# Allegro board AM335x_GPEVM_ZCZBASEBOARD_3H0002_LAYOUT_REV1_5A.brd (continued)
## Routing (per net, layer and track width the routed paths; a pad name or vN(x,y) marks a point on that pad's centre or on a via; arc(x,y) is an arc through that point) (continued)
HDMI_IOVCC: length 34.3
  TOP w0.305: v1(147.1,29.76) 146.98,29.76 146.54,30.19 U10.3 ; U10.46 135.29,33.19 v1(135.04,33.44) ; U10.21 v1(144.13,39.23)
  TOP w0.508: FB12.1 v1(164.88,22.26) v1(164.88,23.41) ; v1(147.1,29.76) 147.99,29.76 v1(148.12,29.88)
  BOTTOM w0.508: 147.99,29.76 v1(148.12,29.88) ; 147.99,29.76 147.99,29.26 147.61,28.88 147.61,26.07 149.39,24.29 163.99,24.29 v1(164.88,23.41) v1(164.88,22.26) ; 147.99,29.76 v1(147.1,29.76) 146.34,29.76 C151.1 ; C150.1 135.29,33.69 v1(135.04,33.44) ; v1(144.13,39.23) 144.13,38.57 C152.1
HDMI_LSOE: length 4.2
  TOP w0.121: v1(136.18,16.17) 136.35,16 U11.5
  BOTTOM w0.121: R322.1 137.45,14.9 v1(136.18,16.17)
HDMI_PCLK: length 69.5
  TOP w0.121: v1(125.39,76.87) 125.89,76.87 126.02,76.75 R307.1 ; v1(146.09,43.47) 146.09,40.6 145.27,39.79 143.9,39.79 143.63,39.52 U10.22 ; v1(144.94,48.92) 145.08,49.06 147.13,49.06 147.26,49.19 147.26,52.03 147.13,52.16 135.83,52.16 133.51,49.85 v1(131.04,49.85)
  BOTTOM w0.121: v1(146.09,43.47) 146.09,46.14 144.49,47.74 144.49,48.47 v1(144.94,48.92) ; v1(131.04,49.85) 131.04,50.84 132.32,52.12 132.32,61.88 131.69,62.51 131.69,71.3 128.29,74.7 128.29,76.89 127.93,77.25 126.66,77.25 126.28,76.87 v1(125.39,76.87)
HDMI_TX0+: length 27.6
  TOP w0.095: J10.7 149.16,9.52 149.06,9.61 148.89,9.61 148.8,9.71 148.8,11.87 146.14,14.53 144.69,14.53 144.52,14.7 U11.18 142.55,14.7 142.37,14.51 142.15,14.51 139.86,16.8 139.86,20.35 138.7,21.51 138.7,22.86 140.02,24.18 140.02,27.76 140.13,27.87 U10.62
HDMI_TX0-: length 27.6
  TOP w0.095: U10.61 139.63,27.87 139.74,27.76 139.74,24.3 138.42,22.97 138.42,21.4 139.58,20.23 139.58,16.69 142.04,14.23 142.37,14.23 142.55,14.05 U11.17 144.74,14.05 144.94,14.25 146.02,14.25 148.52,11.75 148.52,9.71 148.42,9.61 148.25,9.61 148.16,9.52 J10.9
HDMI_TX1+: length 27.6
  TOP w0.095: J10.4 150.66,9.52 150.56,9.61 150.39,9.61 150.3,9.71 150.3,11.79 145.63,16.46 144.55,16.46 144.37,16.65 U11.21 142.55,16.65 142.37,16.46 142.11,16.46 140.63,17.94 140.63,21.06 139.89,21.79 139.89,22.58 141.52,24.21 141.52,27.76 141.63,27.87 U10.65
HDMI_TX1-: length 27.6
  TOP w0.095: J10.6 149.66,9.52 149.75,9.61 149.92,9.61 150.02,9.71 150.02,11.68 145.51,16.18 144.55,16.18 144.37,16 U11.20 142.55,16 142.37,16.18 141.99,16.18 140.35,17.83 140.35,20.94 139.61,21.68 139.61,22.69 141.24,24.32 141.24,27.76 141.13,27.87 U10.64
HDMI_TX2+: length 27.6
  TOP w0.095: U10.68 143.13,27.87 143.02,27.76 143.02,23.4 141.34,21.72 141.34,18.5 142.08,17.76 142.37,17.76 142.55,17.95 U11.23 144.37,17.95 144.55,17.76 145.65,17.76 151.8,11.61 151.8,9.71 151.89,9.61 152.06,9.61 152.16,9.52 J10.1
HDMI_TX2-: length 27.6
  TOP w0.095: J10.3 151.16,9.52 151.25,9.61 151.42,9.61 151.52,9.71 151.52,11.5 145.53,17.48 144.55,17.48 144.37,17.3 U11.22 142.55,17.3 142.37,17.48 141.96,17.48 141.06,18.38 141.06,21.83 142.74,23.51 142.74,27.76 142.63,27.87 U10.67
HDMI_VSYNC: length 70.3
  TOP w0.121: v1(146.37,74.31) 146.37,74.81 146.19,74.99 145.07,74.99 144.94,74.87 144.94,73.9 144.82,73.77 144.04,73.77 143.92,73.9 143.92,75.02 143.79,75.14 143.04,75.14 142.91,75.02 142.91,73.9 142.79,73.77 142.05,73.77 141.92,73.9 141.92,74.94 R305.1 ; U10.35 137.13,38.92 136.71,39.33 135.26,39.33 133.07,41.51 133.07,43.65 134.41,44.99 134.41,46.33 134.54,46.46 135.17,46.46 135.29,46.34 135.29,44.86 135.41,44.74 135.65,44.74 135.77,44.86 135.77,46.34 135.89,46.46 136.14,46.46 136.26,46.34 136.26,44.86 136.38,44.74 136.62,44.74 136.74,44.86 136.74,46.34 136.86,46.46 137.4,46.46 137.53,46.33 137.53,44.61 137.65,44.49 138.19,44.49 138.31,44.61 138.31,46.33 138.44,46.46 141.07,46.46 141.26,46.27 v1(142.02,46.27)
  BOTTOM w0.121: v1(142.02,46.27) 142.02,54.35 142.11,54.44 145.55,54.44 145.94,54.83 145.94,72.25 146.37,72.68 v1(146.37,74.31)
HDMICONN_CEC: length 12.1
  TOP w0.121: U11.7 138.54,14.7 141.64,11.59 142.02,11.59 142.91,10.7 144.49,10.7 144.61,10.58 145.45,10.58 146.16,9.87 J10.13
HDMICONN_HPLG: length 9.5
  TOP w0.121: U11.10 138.84,12.75 140.75,10.83 140.75,9.66 v1(142.2,8.22) 142.66,8.22 142.86,8.42 J10.19
  BOTTOM w0.121: R304.2 v1(142.2,8.22)
HDMICONN_I2CSCL: length 13.7
  TOP w0.121: v1(145.38,6.26) 145.16,6.48 J10.15 145.16,9.68 144.38,10.45 142.78,10.45 141.95,11.29 141.44,11.29 138.68,14.05 U11.8
  BOTTOM w0.121: v1(145.38,6.26) R276.1
HDMICONN_I2CSDA: length 13
  TOP w0.121: U11.9 138.49,13.4 138.51,13.37 138.85,13.37 141.24,10.98 141.87,10.98 142.66,10.2 143.47,10.2 143.47,10.21 144.05,10.21 144.66,9.59 J10.16 v1(144.66,6.23)
  BOTTOM w0.121: R275.1 144.11,5.68 v1(144.66,6.23)
JTAG_EMU0: length 98.4
  TOP w0.102: v2(79.4,89) U2.C14
  TOP w0.121: v1(22.14,89.19) J2.13 ; v1(34.73,91.69) 35.17,91.69 35.37,91.5 47.08,91.5 48.45,92.86 56.14,92.86 57.23,93.95 59.28,93.95 59.91,93.32 60.94,93.32 62.14,94.53 63.83,94.53 64.67,93.69 65.46,93.69 65.96,93.18 66.14,93.18 66.31,93 67.75,93 68.52,92.23 69.98,92.23 70.3,92.55 v1(70.3,92.68) ; R582.1 v1(14.26,67.14)
  LY3 w0.133: v1(14.26,67.14) 15.66,68.54 16.19,68.54 17.27,69.62 20.68,69.62 21.83,70.77 21.83,74.86 22.3,75.33 22.3,75.7 22.03,75.97 22.03,78.4 22.65,79.01 22.65,82.45 21.83,83.27 21.83,84.44 22.58,85.2 22.58,86.84 22.32,87.1 22.32,87.47 22.58,87.74 22.58,88.11 22.14,88.55 v1(22.14,89.19) 22.14,89.64 24.98,92.48 24.98,92.98 25.49,93.48 30.16,93.48 31.95,91.69 v1(34.73,91.69)
  BOTTOM w0.102: 78.98,89 v2(79.4,89)
  BOTTOM w0.121: R71.1 v1(22.14,89.19) ; v1(70.3,92.68) 70.3,92.38 73.46,89.23 78.75,89.23 78.98,89
JTAG_EMU1: length 95.2
  TOP w0.102: 77.1,89.4 77.5,89 78.6,89 U2.B14
  TOP w0.121: v1(73.06,91.75) 73.07,91.75 73.46,91.36 73.46,90.78 73.6,90.64 74.98,90.64 75.96,89.66 76.84,89.66 77.1,89.4 ; v1(31.91,93.76) 32.57,93.76 32.88,93.46 32.88,92.85 33.35,92.38 47.14,92.38 48.11,93.36 55.92,93.36 57.31,94.75 59.45,94.75 60.23,95.53 62.36,95.53 63.08,96.26 65.33,96.26 65.75,96.68 69.1,96.68 v1(69.41,96.36) ; R583.1 v1(17.56,67.17) 18,67.17 18.13,67.3 v1(25.39,67.3) ; J2.14 v1(31.41,89.19)
  BOTTOM w0.121: v1(31.91,93.76) 31.91,89.7 v1(31.41,89.19) R70.1 30.39,85.71 26.28,81.6 26.28,68.19 v1(25.39,67.3) ; v1(73.06,91.75) 71.9,91.75 70.99,92.66 70.99,93.25 69.61,94.63 69.61,95.41 69.35,95.67 69.35,95.87 69.41,95.92 v1(69.41,96.36)
JTAG_TCK: length 100.1
  TOP w0.102: U2.A12 77.75,87 77.1,87.65
  TOP w0.121: R576.1 v1(9.18,67.22) ; v1(63.66,89) 59.85,89 59.1,89.75 56.26,89.75 54.69,91.31 49.03,91.31 47.32,89.6 35.5,89.6 35.3,89.39 v1(34.86,89.39) ; 77.1,87.65 76.33,88.42 75.37,88.42 74.62,89.17 74.4,89.39 74.36,89.39 69.49,89.39 69.49,89.4 69.26,89.4 67.94,90.72 65.63,90.72 65.51,90.84 v1(65.12,90.84)
  LY3 w0.133: v1(34.86,89.39) 34.35,89.9 31,89.9 30.44,90.46 v1(25.95,90.46) 23.1,87.62 23.1,84.98 22.96,84.83 22.96,84.31 23.17,84.1 23.17,69.12 19.42,65.37 11.04,65.37 v1(9.18,67.22)
  BOTTOM w0.121: v1(25.95,90.46) R75.2 R74.2 ; v1(65.12,90.84) 65.12,90.14 63.98,89 v1(63.66,89)
JTAG_TDI: length 112.5
  TOP w0.102: 77.1,87.12 77.63,86.59 78.61,86.59 U2.B11
  TOP w0.121: v1(21.09,94.22) 21.41,94.53 21.41,94.58 22.36,95.54 J2.3 26.07,95.54 26.45,95.92 26.45,97.32 26.71,97.57 32.02,97.57 32.04,97.6 v1(34.15,97.6) ; v1(33.9,88.23) 34.22,87.91 39.37,87.91 40.44,88.98 47.57,88.98 49.29,90.69 54.4,90.69 56.38,88.71 58.81,88.71 59.41,88.11 v1(63.66,88.11) ; v1(10.15,67.02) 10.55,67.42 10.55,67.63 R577.1 ; 77.1,87.12 76.17,88.05 75.22,88.05 75.22,88.05 74.24,89.02 74.21,89.02 72.26,89.02 71.39,88.15 71.33,88.15 v1(71.02,87.84)
  LY3 w0.133: v1(10.15,67.02) 12,68.87 13.6,68.87 15.25,70.52 20.31,70.52 20.92,71.14 20.92,88.32 20.83,88.41 20.83,88.97 20.67,89.13 20.67,89.5 21.09,89.93 v1(21.09,94.22)
  BOTTOM w0.121: v1(33.9,88.23) 33.9,88.67 33.84,88.73 33.84,97.29 v1(34.15,97.6) ; v1(63.66,88.11) 64.13,88.58 66.97,88.58 68.69,86.85 70.23,86.85 71.02,87.64 v1(71.02,87.84)
JTAG_TDO: length 98.7
  TOP w0.102: 77.1,86.55 77.45,86.2 U2.A11
  TOP w0.121: v1(11.57,67.02) 11.21,67.37 R578.1 ; J2.7 v1(25.95,93) ; 77.1,86.55 75.98,87.67 75.07,87.67 74.09,88.64 74.05,88.64 72.52,88.64 72.37,88.5 71.27,87.4 70.76,87.4 70.58,87.58 70.58,88.26 69.69,89.15 69.16,89.15 67.85,90.45 65.64,90.45 65.27,90.08 65.14,90.08 65.14,90.08 64.03,90.08 63.39,90.72 61.63,90.72 61.56,90.65 56.92,90.65 55.52,92.05 48.72,92.05 47.01,90.34 35.42,90.34 35.2,90.56 v1(34.76,90.56)
  LY3 w0.133: v1(11.57,67.02) 12.02,67.02 12.06,67.06 12.41,67.06 13.04,66.43 14.45,66.43 15.08,67.07 15.08,67.3 15.35,67.57 15.58,67.57 17.37,69.36 20.79,69.36 22.09,70.66 22.09,71.01 22.3,71.22 22.3,74.97 22.56,75.23 22.56,75.81 22.33,76.04 22.33,78.32 22.91,78.9 22.91,82.56 22.49,82.98 22.49,84.74 22.84,85.09 22.84,88.21 22.58,88.47 22.58,89.64 v1(25.95,93) 30.06,93 32.5,90.56 v1(34.76,90.56)
JTAG_TMS: length 116.1
  TOP w0.102: U2.C11 79.41,86.59 v2(79.41,87.41)
  TOP w0.121: v1(18.33,65.85) 13.65,65.85 12.23,67.27 R579.1 ; J2.1 v1(24,97.69) 24.34,98.03 33.96,98.03 33.97,98.04 34.33,98.04 34.34,98.03 42.42,98.03 43.22,98.82 55.89,98.82 56.58,98.13 61.05,98.13 61.42,98.49 63.26,98.49 63.66,98.09 64.27,98.09 64.77,98.59 67.22,98.59 67.98,99.35 68.55,99.92 68.8,99.92 68.8,99.92 v1(69.25,99.92)
  LY4 w0.121: v1(69.25,99.92) 69.25,99.47 68.87,99.1 68.87,95.6 70.9,93.58 70.9,92.5 69.89,91.49 v1(69.86,91.49)
  BOTTOM w0.102: 77.1,88.48 77.52,88.48 78.59,87.41 v2(79.41,87.41)
  BOTTOM w0.121: 77.1,88.48 73.15,88.48 71.81,89.83 71.28,89.83 69.86,91.25 v1(69.86,91.49) ; v1(24,97.69) 22.63,97.69 19.77,94.83 19.77,92.32 19.39,91.93 19.39,90.31 19.52,90.19 19.52,83.32 22.57,80.28 22.57,69.33 19.09,65.85 v1(18.33,65.85)
JTAG_TRSTN: length 108
  TOP w0.102: 77.1,86.17 77.44,85.83 78.4,85.83 78.82,85.4 U2.B10
  TOP w0.121: v1(34.28,89.05) 34.59,88.74 39.63,88.74 40.24,89.35 47.42,89.35 49.13,91.06 54.56,91.06 56.18,89.45 58.65,89.45 59.53,88.56 63.48,88.56 63.48,88.56 63.85,88.56 64.3,89.02 v1(64.71,89.02) ; 77.1,86.17 75.86,87.41 74.97,87.41 73.98,88.4 73.95,88.4 72.62,88.4 71.37,87.15 70.66,87.15 70.51,87.3 70.14,87.67 v1(70.14,87.87) ; J2.2 v1(31.41,96.81) 32.28,96.81 32.29,96.82 32.66,96.82 32.67,96.81 v1(34.28,96.81) ; R580.1 v1(13.25,67.12)
  LY3 w0.133: v1(31.41,96.81) 30.52,95.92 24.42,95.92 21.8,93.31 21.8,92.34 21.57,92.1 21.57,75.87 21.4,75.7 21.4,75.33 21.57,75.17 21.57,70.87 20.57,69.88 15.52,69.88 13.25,67.61 v1(13.25,67.12)
  BOTTOM w0.121: v1(64.71,89.02) 67.78,89.02 68.92,87.87 70.13,87.87 v1(70.14,87.87) ; v1(34.28,89.05) 34.28,89.5 34.28,89.5 34.28,96.37 34.28,96.37 v1(34.28,96.81) ; v1(31.41,96.81) R79.2
LCD_DATA0: length 4.5
  TOP w0.102: 138.01,85.25 J7.4
  TOP w0.121: 138.01,85.25 138.54,85.79 138.95,85.79 139.1,85.94 139.1,86.07 138.88,86.29 138.88,86.34 139.07,86.52 140.02,86.52 140.12,86.42 140.12,86.27 R240.1
LCD_DATA1: length 4.7
  TOP w0.102: 138.04,85.91 136.59,85.91 J7.3
  TOP w0.121: R241.1 139.23,87.03 138.11,85.91 138.04,85.91
LCD_DATA2: length 4.4
  TOP w0.102: J7.6 137.91,83.98 138.04,83.86
  TOP w0.121: 138.04,83.86 138.06,83.83 138.06,83.78 138.24,83.6 138.39,83.6 138.39,83.6 138.52,83.73 138.52,83.81 138.61,83.9 138.78,83.9 138.85,83.83 138.85,83.72 138.98,83.6 139.17,83.6 139.25,83.68 139.25,83.96 139.43,84.14 139.63,84.14 139.65,84.11 140.01,84.11 140.14,83.98 140.14,83.88 R245.1
LCD_DATA3: length 4.5
  TOP w0.121: v1(138.72,84.49) 139.1,84.87 139.61,84.87 R246.1
  BOTTOM w0.102: J7.5 136.54,84.59 137.93,84.59 138.04,84.49
  BOTTOM w0.121: v1(138.72,84.49) 138.04,84.49
LCD_DATA4: length 4.5
  TOP w0.102: 138.04,82.16 137.98,82.21 137.98,82.56 137.83,82.71 J7.8
  TOP w0.121: R251.1 140.13,81.84 140.13,82.01 140.07,82.08 139.53,82.08 139.33,82.28 139.18,82.28 139.1,82.21 139.1,82.03 139,81.93 138.86,81.93 138.63,82.16 138.44,82.16 138.3,82.01 138.18,82.01 138.04,82.16
LCD_DATA5: length 4.5
  TOP w0.121: R252.1 138.85,82.59 v1(138.59,82.84)
  BOTTOM w0.102: 138.04,83.27 137.96,83.35 136.56,83.35 J7.7
  BOTTOM w0.121: 138.04,83.27 138.47,82.84 v1(138.59,82.84)
LCD_DATA6: length 4.5
  TOP w0.102: J8.15 130.67,77.63 130.52,77.79 130.52,78.32
  TOP w0.121: R270.1 129.15,77.76 129.27,77.63 129.27,77.53 129.4,77.41 129.93,77.41 130.06,77.53 130.06,78.32 130.19,78.45 130.39,78.45 130.52,78.32
LCD_DATA7: length 8.6
  TOP w0.121: R259.1 129.2,82.84 v1(129.49,82.55)
  LY3 w0.102: 130.57,81.44 J8.9
  LY3 w0.133: v1(129.49,82.55) 128.1,82.55 127.75,82.9 127.75,83.2 127.88,83.32 129.96,83.32 130.09,83.2 130.09,81.57 130.21,81.44 130.57,81.44
LCD_DATA8: length 9.4
  TOP w0.102: 130.72,82.08 133.46,82.08 133.59,81.95 ; 133.59,80.94 133.49,80.83 132.19,80.83 131.53,80.17 J8.11
  TOP w0.121: R262.1 129.53,80.81 130.14,81.42 130.14,81.78 130.26,81.9 130.26,81.9 130.44,82.08 130.72,82.08 ; 133.59,81.95 133.72,81.95 133.84,81.83 133.84,81.14 133.64,80.94 133.59,80.94
LCD_DATA9: length 4.1
  TOP w0.102: R266.1 129.2,78.78 129.31,78.68 129.31,78.14 129.41,78.04 129.61,78.04 129.71,78.14 129.71,78.68 129.81,78.78 130.54,78.78 130.67,78.9 J8.13
LCD_DATA10: length 10.1
  TOP w0.121: v1(138.72,80.37) 139.18,79.91 139.18,79.67 139.31,79.54 R256.1
  LY3 w0.102: 138.14,81.32 138.01,81.44 J7.10
  LY3 w0.133: 138.14,81.32 138.47,80.99 139.99,80.99 140.09,80.89 140.09,78.68 139.97,78.55 138.85,78.55 138.72,78.68 v1(138.72,80.37)
LCD_DATA11: length 10.7
  TOP w0.121: R267.1 139.1,77.13 v1(138.89,77.34)
  LY3 w0.102: J7.16 138.01,77.63 138.29,77.91 141.67,77.91
  LY3 w0.133: 141.67,77.91 141.79,77.79 141.79,76.62 141.67,76.49 139.13,76.49 138.89,76.73 v1(138.89,77.34)
LCD_DATA12: length 13.1
  TOP w0.121: v1(138.59,81.57) 138.34,81.32 138.34,81.19 138.46,81.07 139.74,81.07 139.86,80.94 R257.1
  BOTTOM w0.102: 138.04,82.42 137.97,82.42 137.63,82.08 136.56,82.08 J7.9
  BOTTOM w0.121: v1(138.59,81.57) 139.31,81.57 139.51,81.77 139.51,84.62 139.41,84.72 139.27,84.72 139.18,84.62 139.18,82.21 139.05,82.08 138.29,82.08 138.21,82.16 138.21,82.3 138.09,82.42 138.04,82.42
LCD_DATA13: length 18.6
  TOP w0.121: R258.1 129.27,81.83 v1(129.53,81.57)
  LY3 w0.102: J8.10 133.59,81.44 ; 130.72,80.57 130.99,80.83 133.59,80.83
  LY3 w0.133: 133.59,81.44 133.67,81.52 133.67,84.45 133.79,84.57 133.96,84.57 134.08,84.45 134.08,84.21 134.23,84.06 134.4,84.06 134.53,83.93 134.53,83.11 134.4,82.98 134.28,82.98 134.15,82.85 134.15,82.57 134.28,82.45 134.43,82.45 134.56,82.32 134.56,82.04 134.43,81.91 134.2,81.91 134.07,81.79 134.07,81.51 134.2,81.38 134.38,81.38 134.5,81.25 134.5,80.96 134.38,80.83 133.59,80.83 ; 130.72,80.57 130.4,80.57 130.26,80.7 130.26,80.83 130.13,80.97 129.37,80.97 128.41,81.93 128.41,82.02 128.54,82.16 128.94,82.16 v1(129.53,81.57)
LCD_DATA14: length 9.2
  TOP w0.102: 138.04,80.17 J7.12 ; 138.04,79.72 138.04,78.88 138.04,78.87
  TOP w0.121: 138.04,79.72 138.16,79.84 138.16,80.05 138.04,80.17 ; R260.1 140.25,78.78 140.25,78.85 140.06,79.03 139.65,79.03 139.57,79.12 139.4,79.12 139.25,78.97 139.25,78.35 139.14,78.24 138.98,78.24 138.87,78.35 138.87,79.72 138.75,79.84 138.57,79.84 138.44,79.72 138.44,78.44 138.33,78.32 138.16,78.32 138.04,78.44 138.04,78.87
LCD_DATA15: length 24.4
  TOP w0.121: R254.1 v1(129.7,83.86)
  LY3 w0.102: 130.55,82.82 130.65,82.71 J8.7
  LY3 w0.133: v1(129.7,83.86) 127.14,83.86 127.01,83.98 127.01,85.41 127.14,85.55 129.82,85.55 129.96,85.68 129.96,85.95 129.82,86.08 127.14,86.08 127.01,86.21 127.01,86.47 127.14,86.6 127.4,86.6 127.65,86.85 127.93,86.85 128.19,86.6 130.29,86.6 130.42,86.47 130.42,85.29 130.28,85.15 128.29,85.15 128.15,85.02 128.15,84.75 128.29,84.62 130.28,84.62 130.42,84.49 130.42,82.95 130.55,82.82
LCD_DATA16: length 64.1
  TOP w0.121: R253.1 97.53,93.41 98.36,93.41 98.64,93.69 98.64,94.62 100.06,96.04 103.21,96.04 104.99,97.82 113.7,97.82 114.03,98.16 115.17,98.16 115.29,98.28 115.29,99.49 115.41,99.61 115.65,99.61 115.77,99.49 115.77,99.32 115.89,99.2 119.3,99.2 119.42,99.08 119.42,98.84 119.3,98.72 115.89,98.72 115.77,98.6 115.77,98.28 115.89,98.16 v1(116.34,98.16)
  LY4 w0.133: v1(117,86.38) 117,86.96 116.78,87.18 116.78,93.84 116.79,93.86 116.79,94.43 116.47,94.75 116.47,95.62 116.34,95.75 115.79,95.75 115.66,95.88 115.66,96.15 115.79,96.28 116.34,96.28 116.47,96.42 116.47,98.03 v1(116.34,98.16)
  BOTTOM w0.102: 130.72,82.16 130.77,82.1 132.09,82.1 132.7,82.71 J8.8
  BOTTOM w0.121: v1(117,86.38) 117.26,86.63 126.85,86.63 127.14,86.35 127.14,84.34 127.7,83.78 129.1,83.78 130.72,82.16
LCD_DATA17: length 46.1
  TOP w0.121: R248.1 103.27,94.27 104.79,95.79 117.25,95.79 117.54,96.07 v1(118.41,96.07)
  LY4 w0.133: v1(118.41,96.07) 118.41,95.38 118.54,95.24 119.54,95.24 119.67,95.11 119.67,94.84 119.54,94.71 118.54,94.71 118.41,94.58 118.41,94.31 118.54,94.18 119.54,94.18 119.67,94.04 119.67,93.78 119.54,93.64 118.54,93.64 118.41,93.51 118.41,89.95 118.02,89.56 v1(118.02,87.46)
  BOTTOM w0.102: 130.72,84.75 130.72,84.54 131.28,83.98 J8.5
  BOTTOM w0.121: v1(118.02,87.46) 118.97,87.46 119.16,87.28 119.52,87.28 119.71,87.46 127.7,87.46 130.03,85.13 130.34,85.13 130.72,84.75
LCD_DATA18: length 53.5
  TOP w0.102: J8.6 132.12,83.35 130.85,83.35 130.72,83.48
  TOP w0.121: v1(98.92,89.04) 98.92,88.9 98.79,88.78 98,88.78 97.9,88.87 97.52,88.87 97.51,88.86 R247.1 ; v1(106.78,88.24) 106.78,87.26 108.11,85.93 108.11,83.4 109.55,81.96 112.77,81.96 114.37,83.56 122.4,83.56 122.68,83.84 122.85,83.84 123.19,83.5 123.36,83.5 123.53,83.67 123.53,83.84 123.19,84.18 123.19,84.35 123.36,84.52 123.53,84.52 123.87,84.19 124.04,84.19 124.21,84.36 124.21,84.53 123.87,84.86 123.87,85.03 124.04,85.21 124.21,85.21 124.55,84.87 124.72,84.87 124.89,85.04 124.89,85.21 124.55,85.55 124.55,85.72 124.72,85.89 124.9,85.89 125.23,85.55 125.4,85.55 125.57,85.72 125.57,85.89 125.24,86.23 125.24,86.4 126,87.16 127.55,87.16 127.67,87.03 127.67,86.3 127.55,86.18 126.17,86.18 126.05,86.06 126.05,85.81 126.17,85.69 127.55,85.69 127.67,85.57 127.67,85.25 128.48,84.45 129.75,84.45 130.72,83.48
  BOTTOM w0.121: v1(98.92,89.04) 104.91,89.04 105.71,88.24 106.77,88.24 v1(106.78,88.24)
LCD_DATA19: length 30.1
  TOP w0.121: R264.1 112.41,86.12 115,86.12 115.18,85.94 116.82,85.94 116.82,85.94 117.19,85.94 117.19,85.94 117.68,85.94 118.33,85.29 v1(118.77,85.29)
  LY3 w0.102: 130.63,79.96 131.03,79.56 133.16,79.56 133.82,78.9 J7.13
  LY3 w0.133: 130.63,79.96 129.88,80.71 129.09,80.71 126.55,83.25 126.55,85.91 125.34,87.13 122.06,87.13 120.22,85.29 v1(118.77,85.29)
LCD_DATA20: length 26.6
  TOP w0.102: 130.72,85.25 J8.3
  TOP w0.121: R243.1 112.48,82.71 112.84,83.07 112.84,83.36 112.72,83.48 112.48,83.48 112.36,83.6 112.36,83.93 112.48,84.05 122.19,84.05 125.8,87.67 127.93,87.67 128.18,87.41 128.18,85.52 128.75,84.95 130.28,84.95 130.59,85.25 130.72,85.25
LCD_DATA21: length 35.6
  TOP w0.102: 130.72,85.89 132.12,85.89 J8.4
  TOP w0.121: 130.72,85.89 130.02,85.19 128.96,85.19 128.43,85.73 128.43,87.52 128.31,87.64 128.31,87.67 128.06,87.92 125.7,87.92 122.09,84.3 114.34,84.3 113.96,84.69 113.96,84.9 114.08,85.03 117.21,85.03 117.33,85.15 117.33,85.57 117.21,85.69 116.72,85.69 116.72,85.69 112.74,85.69 112.3,85.26 111.84,85.26 111.34,85.76 R242.1
LCD_DATA22: length 52.5
  TOP w0.121: R263.1 v1(104.81,91.6)
  LY3 w0.133: v1(140.17,89.65) 139.85,89.96 139.85,90.01 139.83,90.01 139.56,90.28 139.56,90.63 139.08,91.12 v1(137.36,91.12)
  BOTTOM w0.102: 138.04,78.9 J7.14
  BOTTOM w0.121: 138.04,78.9 139,78.9 140.8,80.7 140.8,88.91 140.48,89.22 140.48,89.34 v1(140.17,89.65) ; v1(137.36,91.12) 136.97,91.12 136.18,90.33 132.49,90.33 131.9,90.92 131.86,90.92 131.07,91.71 130.05,91.71 129.12,90.77 128.68,90.33 125.3,90.33 124.97,90.66 112.1,90.66 111.85,90.91 108.62,90.91 107.92,91.6 v1(104.81,91.6)
LCD_DATA23: length 44.4
  TOP w0.121: v1(128.89,87.59) 128.13,88.35 128.13,88.48 128.01,88.6 120.22,88.6 v1(119.34,87.72) ; R261.1 108.77,91.6 110.3,93.13 114.92,93.13 115.05,93 118.12,93 118.53,93.41 v1(119.98,93.41)
  LY3 w0.102: v1(128.89,87.59) 129.6,87.59 129.64,87.63 129.74,87.63 129.78,87.67 130.14,87.67 130.21,87.59 130.54,87.59 130.72,87.41 133.92,87.41 134.81,86.52 134.81,85.36 135.04,85.13 135.04,80.25 135.11,80.17 J7.11
  LY4 w0.133: v1(119.98,93.41) 119.34,92.77 v1(119.34,87.72)
LCD_DEN: length 20.6
  TOP w0.102: v1(130.01,76.36) 129.32,76.36 R273.1
  BOTTOM w0.102: 133.72,77.99 133.72,77.48 133.59,77.36 133.59,77.33 ; 130.72,77 130.73,76.99 133.53,76.99 133.59,77.05 ; 133.57,75.14 133.57,75.58 133.44,75.71 130.72,75.71 ; J8.17 130.72,76.36
  BOTTOM w0.121: 130.72,77 130.64,77 130.52,77.12 130.52,79.16 130.39,79.29 130.14,79.29 130.01,79.16 v1(130.01,76.36) ; 133.72,77.99 133.84,78.12 134.12,78.12 134.25,77.99 134.25,75.19 134.08,75.02 133.7,75.02 133.57,75.14 ; 130.72,75.71 130.54,75.71 130.42,75.84 130.42,76.24 130.54,76.36 130.72,76.36 ; 133.59,77.33 133.59,77.05
LCD_HSYNC: length 6
  TOP w0.102: 130.72,75.7 132.09,75.7 J8.18
  TOP w0.121: 130.72,75.7 130.62,75.7 130.45,75.54 130.09,75.54 129.96,75.41 129.96,75.18 130.09,75.06 130.16,75.06 130.29,74.93 130.29,74.58 130.16,74.46 129.55,74.46 129.3,74.71 R272.1
LCD_I2C_SCL: length 19.6
  TOP w0.102: 133.59,78.07 J8.14
  TOP w0.121: 133.59,78.07 133.59,74.64 134,74.23 135.34,74.23 138.29,74.23 138.44,74.37 139.01,74.37 140.06,73.32 146.09,73.32 146.85,72.55 146.85,71.79
LCD_I2C_SDA: length 17.1
  TOP w0.102: 138.34,77 136.56,77 J7.15
  TOP w0.121: 138.34,77 138.72,76.62 142.02,76.62 142.99,75.65 146.44,75.65 147.23,74.87 147.23,73.67 147.35,73.55 147.35,71.03 146.85,70.52
LCD_PCLK: length 4.4
  TOP w0.102: J8.16 132.63,77.63 131.99,77 130.72,77
  TOP w0.121: R269.1 128.94,77 130.72,77
LCD_VSYNC: length 4.5
  TOP w0.102: J7.17 136.59,75.7 138.04,75.7
  TOP w0.121: R271.1 138.77,74.97 138.04,75.7
LCDA_PIN18: length 2.8
  TOP w0.102: 138.04,76.36 J7.18
  TOP w0.121: R274.2 138.85,75.98 138.47,76.36 138.04,76.36
MCASP0_ACLKR: length 27
  TOP w0.121: R218.1 v1(70.62,107.48)
  BOTTOM w0.121: v1(70.62,107.48) 70.62,108.13 70.82,108.32 70.82,116.79 67.26,120.34 67.21,120.34 67.22,120.35 J6.17
MCASP0_ACLKX: length 7.1
  TOP w0.121: v1(87.84,131.23) 87.54,131.53 R194.2
  BOTTOM w0.121: v1(87.84,131.23) 88.49,130.58 88.49,126.59 J6.1
MCASP0_AHCLKR: length 45.2
  TOP w0.121: R211.2 82.21,155.61 81.68,155.09 71.02,155.09 v1(70.52,155.59)
  BOTTOM w0.121: v1(70.52,155.59) 70.16,155.23 70.16,151.82 69.89,151.55 69.89,148.14 70.16,147.87 70.16,140.63 70,140.46 70,136.4 71.2,135.19 71.2,127.78 72.3,126.68 J6.13
MCASP0_AHCLKX: length 20.9
  TOP w0.121: J6.27 v1(45.5,125.64) ; R234.1 v1(45.17,114.59)
  BOTTOM w0.121: v1(45.5,125.64) 45.5,119.75 45.17,119.42 v1(45.17,114.59)
MCASP0_AXR0: length 1.8
  BOTTOM w0.121: R203.2 J6.7
MCASP0_AXR1: length 8.4
  TOP w0.121: R227.1 52.48,126.66 57.43,126.66 58.46,125.64 J6.23
MCASP0_FSR: length 31.2
  TOP w0.121: v1(68.36,123.86) 64.78,123.86 63.83,124.81 62.97,124.81 J6.21 ; v1(73.44,103.03) 73.7,102.78 R224.1
  BOTTOM w0.121: v1(68.36,123.86) 68.79,123.43 68.79,122.54 69.57,121.77 70.27,121.77 72.86,119.18 72.86,104.96 73.44,104.38 v1(73.44,103.03)
MCASP0_FSX: length 1.8
  BOTTOM w0.121: R199.2 J6.5
MMC2_CLK: length 39.9
  TOP w0.121: U28.13 21.76,106.66 4.89,106.66 4.61,106.94 4.61,107.33 4.74,107.45 7.64,107.45 7.76,107.58 7.76,107.99 7.64,108.11 v1(4.61,108.11)
  BOTTOM w0.121: R485.1 5.12,111.16 4.74,110.78 4.1,110.78 3.85,110.53 3.85,106.72 3.97,106.59 7.81,106.59 7.94,106.72 7.94,107.2 7.81,107.33 5.8,107.33 5.68,107.45 5.68,108.42 5.55,108.55 4.74,108.55 4.61,108.42 v1(4.61,108.11)
MMC2_CMD: length 40.1
  TOP w0.121: U28.12 20.44,107.37 19.98,106.91 17.87,106.91 17.74,107.04 17.74,107.83 17.61,107.96 13.63,107.96 13.5,107.83 13.5,107.56 13.63,107.43 16.8,107.43 16.93,107.3 16.93,107.04 16.8,106.91 8.14,106.91 8.01,107.04 8.01,109 7.89,109.13 4.74,109.13 4.62,109 4.62,108.88 4.49,108.75 3.85,108.75 3.59,109 3.59,109.51 2.83,110.27 2.83,115.43 2.96,115.56 3.62,115.56 3.75,115.43 3.75,113.58 3.87,113.45 v1(4.36,113.45)
  BOTTOM w0.121: R486.1 v1(4.36,113.45)
MMC2_D0: length 40.6
  TOP w0.121: v1(4.36,116.88) 4.04,116.88 3.91,116.75 3.91,116.12 3.79,115.99 3.49,115.99 3.36,116.12 3.36,119.26 3.24,119.39 2.7,119.39 2.58,119.26 2.58,108.62 4.78,106.42 19.74,106.42 20.81,105.35 21.98,105.35 22.27,105.64 U28.14
  BOTTOM w0.121: v1(4.36,116.88) 4.99,116.24 4.99,115.86 5.12,115.73 R487.1
MMC2_D1: length 39.8
  TOP w0.121: U28.15 22.77,105.32 22.52,105.07 20.55,105.07 19.45,106.17 4.65,106.17 2.32,108.5 2.32,119.7 2.45,119.82 3.54,119.82 3.67,119.7 3.67,118.53 3.8,118.4 4.36,118.4 4.48,118.53 v1(4.48,119.16)
  BOTTOM w0.121: R488.1 v1(4.48,119.16)
MMC2_D2: length 39.5
  TOP w0.121: U28.8 20.47,109.37 19.87,109.97 v1(19.26,109.97) ; v1(18.63,105.7) 18.41,105.92 4.52,105.92 2.07,108.37 2.07,119.9 2.48,120.31 v1(4.48,120.31)
  BOTTOM w0.121: v1(18.63,105.7) 18.63,108.22 19.26,108.85 v1(19.26,109.97) ; R489.1 v1(4.48,120.31)
MMC2_D3: length 40.5
  TOP w0.121: v1(19.34,107.86) 19.85,108.37 U28.10 ; v1(19.34,105.65) 19.34,105.62 18.98,105.26 18.41,105.26 17.99,105.67 4.38,105.67 1.82,108.24 1.82,120.56 v1(4.36,123.1)
  BOTTOM w0.121: R490.1 5.12,123.1 v1(4.36,123.1) ; v1(19.34,107.86) v1(19.34,105.65)
MMC2_SDIO_SEL: length 3.4
  TOP w0.121: R515.1 R516.2 26.31,109.87 U28.24
MMC_CD: length 71.8
  TOP w0.121: v1(66.55,92.3) 66.55,92.3 67.75,92.3 69.02,91.03 69.97,91.03 70.36,90.64 71.79,90.64 72.3,91.15 R380.1 ; J13.15 64.3,146.44 64.76,145.99 64.76,144.21 64.63,144.08 64.28,144.08 U21.3 64.14,144.18 R378.1 v1(62.27,144.18)
  BOTTOM w0.121: v1(66.55,92.3) 66.56,92.31 66.56,92.77 66.39,92.94 66.39,99.28 66.5,99.38 66.5,101.95 66.91,102.36 66.91,105.22 66.21,105.92 66.21,117.76 60.94,123.03 60.94,133.97 62.52,135.55 62.52,136.62 62.46,136.68 62.46,137.77 63.16,138.47 63.92,138.47 64.43,138.98 64.43,143.04 63.28,144.18 v1(62.27,144.18)
MMC_CLK: length 42.1
  TOP w0.121: J13.20 53.03,149.78 53.15,149.9 56.18,149.9 56.3,149.78 56.3,148.58 J13.5 56.37,143.72 56.68,143.42 U19.1 57.71,142.94 57.57,142.8 57.57,141.92 57.7,141.79 60.29,141.79 61.07,142.58 65.23,142.58 66.54,143.89 72.68,143.89 72.88,143.68 77.61,143.68 77.82,143.89 81.3,143.89 81.8,144.39 81.81,144.39 82.36,144.94 83.21,144.94 v1(83.53,145.25)
  BOTTOM w0.121: R398.1 83.6,145.17 v1(83.53,145.25)
MMC_CMD: length 51.3
  TOP w0.121: v1(58.97,145.58) 58.71,145.32 U19.7 ; v1(55.41,150.85) 55.34,150.79 49.6,150.79 48.88,150.06 J13.2 48.73,148.35 48.73,147.28 v1(48.55,147.1) ; J13.17 v1(59.73,147.11)
  LY3 w0.133: v1(80.78,145.55) 74.59,145.55 73.95,146.19 64.76,146.19 64.08,145.51 62.97,145.51 62.8,145.68 59.65,145.68 59.55,145.58 v1(58.97,145.58)
  BOTTOM w0.121: R366.1 v1(48.55,147.1) ; v1(80.78,145.55) 81.19,145.15 R397.1 ; v1(55.41,150.85) 55.41,150.79 55.54,150.66 56.68,150.66 56.81,150.53 56.81,150.28 56.93,150.16 59.48,150.16 60.36,151.04 61.51,151.04 61.63,150.91 61.63,148.75 61.51,148.63 59.85,148.63 J13.17 v1(59.73,147.11) 58.97,146.35 v1(58.97,145.58)
MMC_D0: length 47.7
  TOP w0.121: v1(77.99,145.1) 77.99,144.41 77.51,143.93 72.99,143.93 72.78,144.13 66.44,144.13 65.14,142.84 60.77,142.84 60.03,142.1 58.44,142.1 v1(58.01,142.53) 58.01,142.84 58.13,142.96 58.13,143.34 U19.2 ; v1(61.38,147.1) 61.38,148.42 J13.7 61.12,148.68 61.12,149.77 61,149.9 56.67,149.9 56.43,150.14 50.96,150.14 50.53,149.71 J13.22 50.68,148.34 50.68,147.26 v1(50.84,147.1)
  BOTTOM w0.121: v1(50.84,147.1) R367.1 ; v1(77.99,145.1) 78.02,145.1 R399.1 ; v1(61.38,147.1) 61.38,146.57 60.95,146.14 60.69,146.14 59.37,144.82 58.58,144.82 58.32,144.55 58.32,142.84 v1(58.01,142.53)
MMC_D1: length 42.2
  TOP w0.121: v1(49.69,147.1) 49.69,148.47 J13.23 49.72,150.01 50.1,150.39 56.56,150.39 56.81,150.15 62.87,150.15 63,150.02 J13.8 63,146.95 61.89,145.83 61.89,145.21 60.31,143.63 60.31,142.86 59.88,142.43 58.94,142.43 v1(58.8,142.57) 58.71,142.66 U19.3
  LY3 w0.133: v1(71.03,145.2) 69.73,143.89 66.68,143.89 65.35,142.57 v1(58.8,142.57)
  BOTTOM w0.121: R368.1 v1(49.69,147.1) ; R400.1 v1(71.03,145.2)
MMC_D2: length 42.7
  TOP w0.121: v1(58.33,150.91) 57.7,151.54 47.66,151.54 46.45,150.34 44.42,150.34 43.88,149.79 J13.9 43.85,148.48 v1(43.85,147.1) ; U19.6 59.98,144.69 v1(60.18,144.89) 62.15,146.86 v1(62.15,147.1) J13.24
  LY3 w0.133: v1(60.18,144.89) 62.55,144.89 63.3,144.14 66.44,144.14 66.51,144.21 67.18,144.21 v1(68.19,145.22)
  BOTTOM w0.121: R369.1 v1(43.85,147.1) ; v1(68.19,145.22) 68.19,145.2 68.49,144.91 R401.1 ; v1(62.15,147.1) 62.15,151.28 61.51,151.93 59.35,151.93 v1(58.33,150.91)
MMC_D3: length 41.8
  TOP w0.121: U19.8 v1(58.21,145.45) 58.21,145.96 58.58,146.34 60.17,146.34 60.52,146.69 v1(60.52,147.13) J13.16 ; v1(46.38,147.12) J13.1 46.45,148.58 46.45,149.83 47.92,151.29 57.06,151.29 v1(57.44,150.91)
  LY3 w0.133: v1(58.21,145.45) 58.52,145.13 58.78,145.13 59.79,145.13 60,145.34 62.61,145.34 63.44,144.51 65.42,144.51 66.1,145.2 v1(66.97,145.2)
  BOTTOM w0.121: v1(60.52,147.13) 61.89,148.5 61.89,151.04 61.25,151.68 59.85,151.68 59.6,151.42 59.6,150.66 59.34,150.4 57.82,150.4 57.44,150.78 v1(57.44,150.91) ; R365.1 46.38,147.85 v1(46.38,147.12) ; R396.1 v1(66.97,145.2)
MMC_D4: length 49.4
  TOP w0.121: U20.1 72.71,148.87 72.71,148.6 v1(72.94,148.37) ; v1(72.17,163.23) 65.19,163.23 64.81,163.61 64.81,167.04 63.54,168.31 48.3,168.31 47.6,167.62 J13.10 v1(47.6,164.25)
  BOTTOM w0.121: v1(72.17,163.23) 72.17,152.95 72.55,152.56 72.55,148.75 v1(72.94,148.37) ; v1(47.6,164.25) 47.6,165.2 R370.1
MMC_D5: length 45.6
  TOP w0.121: v1(50.12,164.25) 50.12,165.48 J13.11 50.1,167.45 50.58,167.93 63.16,167.93 64.3,166.79 64.3,163.36 64.93,162.72 v1(73.06,162.72) ; U20.2 v1(73.32,149.52)
  BOTTOM w0.121: v1(73.06,162.72) 73.06,150.53 73.32,150.28 v1(73.32,149.52) ; v1(50.12,164.25) 50.12,165.21 R371.1
MMC_D6: length 34.4
  TOP w0.121: v1(57.6,164.31) J13.12 57.6,166.44 57.57,166.47 57.57,166.79 57.95,167.17 62.52,167.17 63.28,166.41 63.28,162.85 63.98,162.15 v1(71.16,162.15) ; v1(70.52,150.15) 70.65,150.02 U20.7
  BOTTOM w0.121: v1(71.16,162.15) 71.16,154.98 70.52,154.34 v1(70.52,150.15) ; v1(57.6,164.31) 57.6,165.23 R372.1
MMC_D7: length 32
  TOP w0.121: v1(60.11,164.38) 60.11,165.49 J13.13 60.1,166.44 60.2,166.53 62.39,166.53 62.9,166.03 62.9,162.72 63.92,161.71 69.89,161.71 70.14,161.45 v1(71.67,161.45) ; U20.8 70.65,149.52 v1(70.52,149.39)
  BOTTOM w0.121: v1(70.52,149.39) 70.96,149.83 70.96,154.02 71.67,154.72 v1(71.67,161.45) ; R373.1 v1(60.11,164.38)
MMC_WP: length 58.1
  TOP w0.121: R379.1 76.02,106.46 75.77,106.71 70.77,106.71 70.01,105.96 v1(67.22,105.96) ; U21.5 65.5,145.17 v1(65.5,145.58) J13.14
  BOTTOM w0.121: v1(67.22,105.96) 66.71,106.47 66.71,118.33 63.48,121.55 63.43,121.55 62.39,122.59 62.39,124.55 63.09,125.25 63.09,126.03 62.53,126.59 62.39,126.59 61.19,127.79 61.19,128.57 61.24,128.63 61.24,129.19 61.89,129.84 61.89,133.85 64.67,136.63 64.67,144.75 v1(65.5,145.58)
MVRK_GPIO1_D0: length 6.4
  TOP w0.121: R437.1 114.34,161.07 J16.2
MVRK_GPIO1_D1: length 75.9
  TOP w0.121: v1(104.94,155.1) 104.94,155.31 104.05,156.2 104.05,163.61 104.3,163.87 109,163.87 J16.4
  LY4 w0.133: v1(104.94,155.1) 105.59,154.45 105.59,123.86 104.25,122.52 104.25,119.85 104.56,119.54 104.56,114.92 102.27,112.64 v1(102.27,110.08)
  BOTTOM w0.121: v1(102.27,110.08) 103.21,109.14 103.21,101.71 103.75,101.18 103.75,98.02 103.87,97.89 R439.1
MVRK_GPIO1_D2: length 72.8
  TOP w0.121: v1(104.94,154.34) 105.57,154.98 105.57,155.99 104.43,157.13 104.43,163.24 104.81,163.61 107.61,163.61 107.86,163.36 J16.6
  LY4 w0.133: v1(101.45,110.08) 101.45,115.57 101.8,115.92 101.8,121.08 105.14,124.42 105.14,154.14 v1(104.94,154.34)
  BOTTOM w0.121: R440.1 102.78,98.72 102.47,99.03 102.47,109.06 v1(101.45,110.08)
MVRK_GPIO1_D3: length 67.4
  TOP w0.121: J16.8 106.24,161.55 106.24,154.31 v1(106.21,154.28)
  LY4 w0.133: v1(103.1,110.08) 103.1,112.57 104.89,114.36 104.89,119.75 104.59,120.05 104.59,122.19 105.85,123.46 105.85,153.92 v1(106.21,154.28)
  BOTTOM w0.121: v1(103.1,110.08) 103.54,109.64 103.54,103.85 103.86,103.53 103.86,101.64 105.23,100.27 105.23,99.45 105.32,99.36 R441.1
MVRK_GPIO1_D4: length 6.6
  TOP w0.121: J16.10 101.89,161.58 101.89,158.56 102.91,157.54 R442.1
MVRK_GPIO1_D5: length 6.4
  TOP w0.121: R444.1 100.37,157.67 101.13,158.43 101.13,161.58 J16.12
MVRK_GPIO1_D6: length 6.5
  TOP w0.121: R446.1 97.45,157.82 96.66,158.61 96.66,161.43 J16.14
MVRK_GPIO1_D7: length 6.1
  TOP w0.121: R447.1 94.27,156.76 94.27,161.58 J16.16
MVRK_GPIO1_LATCHEN: length 6.5
  TOP w0.121: R450.1 90.08,157.06 89.17,157.97 89.17,161.56 J16.20
MVRK_I2C_SCL: length 93.2
  TOP w0.121: v1(73.57,159.83) 75.14,159.83 79.44,164.12 98.64,164.12 99.35,163.41 99.35,160.82 J16.11 ; R443.2 76.24,101.7 v1(75.66,102.27)
  BOTTOM w0.121: v1(73.57,159.83) 73.57,155.46 73.58,155.45 73.58,150.53 73.76,150.36 73.76,148.93 73.58,148.75 73.58,141.56 71.98,139.96 71.98,136.16 71.45,135.63 71.45,130.55 73.25,128.75 73.25,122.53 73.25,122.32 75.05,120.52 75.05,120.43 75.06,120.41 75.66,119.81 75.66,103.23 75.82,103.07 75.82,102.43 v1(75.66,102.27)
MVRK_I2C_SDA: length 91.4
  TOP w0.121: R445.2 v1(75.22,105.96) ; J16.13 98.82,161.05 98.82,163.16 98.26,163.71 79.64,163.71 75.17,159.24 v1(69.81,159.24)
  BOTTOM w0.121: v1(75.22,105.96) 74.95,106.23 74.95,120.17 74.8,120.32 74.8,120.42 70.96,124.26 70.96,134.86 69.75,136.06 69.75,140.57 69.92,140.73 69.92,147.74 69.63,148.02 69.63,151.68 69.92,151.96 69.92,155.49 69.81,155.59 v1(69.81,159.24)
MVRK_SPI_CS: length 3.3
  TOP w0.121: R452.2 J16.23
MVRK_SPI_SCLK: length 34
  TOP w0.121: v1(87.35,130.72) 87.1,130.97 R448.2
  BOTTOM w0.121: J16.17 92.62,156.53 87.22,151.13 87.22,148.87 85.28,146.93 85.28,135.7 87.22,133.76 87.22,131.34 87.35,131.21 v1(87.35,130.72)
MVRK_SPI_SIMO: length 3.2
  TOP w0.121: R451.2 J16.21
MVRK_SPI_SOMI: length 54.9
  TOP w0.121: v1(94.91,123.68) 94.51,123.29 89.75,123.29 89.05,122.59 R449.2
  BOTTOM w0.121: v1(94.91,123.68) 94.91,123.73 95.03,123.86 95.03,128.11 95.48,128.55 95.48,130.84 95.03,131.29 95.03,132.69 95.1,132.76 95.1,132.78 95.16,132.84 95.16,133.08 95.66,133.58 95.66,134.21 95.4,134.46 95.4,134.74 95.16,134.98 95.16,135.86 95.19,135.89 95.34,136.04 95.34,143.45 95.53,143.64 95.53,144.21 95.16,144.58 95.16,147.99 93.46,149.69 93.46,158.46 93.79,158.79 93.79,160.41 93.32,160.88 91.03,160.88 J16.19
MVRK_UART_RXD: length 120.9
  TOP w0.121: J16.3 111.67,161.2 111.67,163.36 110.58,164.45 79.29,164.45 75.14,160.31 69.15,160.31 v1(68.03,159.19) ; v1(73.76,94.27) R438.2
  BOTTOM w0.121: v1(73.76,94.27) 73.76,94.59 73.44,94.91 73.44,99.32 70.84,101.92 70.84,103.61 70.87,103.64 70.87,105.99 70.18,106.68 70.18,111.01 70.57,111.4 70.57,116.55 66.33,120.79 66.33,123.28 66.12,123.49 66.12,132.77 66.97,133.62 66.97,134.44 67.29,134.76 67.29,140.92 67.5,141.13 67.5,145.76 67.84,146.1 67.84,146.1 68.11,146.36 68.11,152.18 68.33,152.4 68.33,156.26 68.03,156.56 v1(68.03,159.19)
MVRK_UART_TXD: length 56.1
  TOP w0.121: v1(82.76,145.71) 93.08,145.71 93.27,145.9 94.45,145.9 97.25,148.69 112.61,148.69 113.06,149.14 v1(113.42,149.14) ; R436.2 v1(81.95,134.28)
  BOTTOM w0.121: v1(113.42,149.14) 113.42,152.59 112.94,153.07 J16.1 ; v1(82.76,145.71) 82.76,144.96 82.46,144.66 82.46,135.93 81.95,135.42 v1(81.95,134.28)
NAND_ADVN_ALE: length 12.2
  TOP w0.121: R137.1 141.48,98.34 142.14,99 144.18,99 144.61,99.42 149.61,99.42 151.26,97.78 U9.17
NAND_BE0N_CLE: length 11.4
  TOP w0.121: U9.16 150.76,95.93 150.63,95.8 148.12,95.8 147.54,95.22 147.54,95.16 147.29,94.91 143.29,94.91 142.4,95.8 R136.1
NAND_CSN: length 9
  TOP w0.121: R135.1 141.64,97.07 143.42,95.29 147.04,95.29 v1(147.1,95.35) 147.26,95.5 U9.9
  BOTTOM w0.121: R132.1 v1(147.1,95.35)
NAND_D0: length 19.5
  TOP w0.121: R140.1 150.1,106.84 152.76,109.51 U9.29
NAND_D1: length 18.3
  TOP w0.121: U9.30 152.26,109.84 150.66,108.24 R141.1
NAND_D2: length 16.6
  TOP w0.121: R142.1 150.53,109.64 151.76,110.87 U9.31
NAND_D3: length 14.7
  TOP w0.121: R143.1 149.77,110.91 151.26,112.4 U9.32
NAND_D4: length 9
  TOP w0.121: U9.41 146.76,113.49 145.83,112.56 141.52,112.56 R144.1
NAND_D5: length 7.2
  TOP w0.121: U9.42 146.26,114.64 145.2,113.58 R145.1
NAND_D6: length 7
  TOP w0.121: R146.1 142.15,113.96 145.07,113.96 145.76,114.65 U9.43
NAND_D7: length 6.6
  TOP w0.121: R147.1 141.18,116.19 141.18,115.68 142.53,114.34 144.31,114.34 145.26,115.29 U9.44
NAND_D8: length 75.5
  TOP w0.121: v1(124.24,94.4) 124.06,94.22 117.36,94.22 116.74,93.6 115.86,93.6 115.53,93.93 107.29,93.93 107,93.64 R148.1 ; v1(140.12,117.26) 143.16,120.3 152.36,120.3 154.26,118.4 U9.26
  BOTTOM w0.121: v1(124.24,94.4) 124.69,94.84 128.94,94.84 129.39,94.4 131.99,94.4 132.43,94.84 133.32,94.84 133.64,95.16 135.93,95.16 136.94,96.18 136.94,96.81 136.05,97.7 135.17,97.7 134.7,98.16 134.7,99.22 135.69,100.2 136.19,100.2 138.85,102.86 138.85,104.62 139.17,104.94 139.17,113.26 140.12,114.21 v1(140.12,117.26)
NAND_D9: length 70.3
  TOP w0.121: v1(154.09,115.1) 153.76,115.43 U9.27 ; R149.1 104.69,94.27 104.69,94.53 105.11,94.95 105.91,94.95 106.34,94.53 123.4,94.53 124.14,95.27 127.19,95.27 127.44,95.52 128.68,95.52 131.24,98.08 136.74,98.08 138.91,100.26 143.86,100.26 144.17,100.57 153.41,100.57 154.09,99.89 v1(154.09,99.88)
  BOTTOM w0.121: v1(154.09,115.1) v1(154.09,99.88)
NAND_D10: length 71
  TOP w0.121: U9.28 v1(153.26,115.16) ; v1(153.96,93) 153.07,93 151.74,91.67 150.79,91.67 149.68,90.56 144.72,90.56 143.31,89.15 132.45,89.15 131.49,90.11 129.95,90.11 128.99,89.15 117.2,89.15 116.86,88.82 110.53,88.82 R150.1
  BOTTOM w0.121: v1(153.26,115.16) 153.26,98.63 153.96,97.93 v1(153.96,93)
NAND_D11: length 79.1
  TOP w0.102: 135.17,84.64 137.96,84.64 138.04,84.72 ; 133.59,84.64 130.82,84.64 130.77,84.7
  TOP w0.121: 135.17,84.64 134.75,85.06 134.01,85.06 133.59,84.64 ; 138.04,84.72 138.82,85.51 142.29,85.51 142.48,85.7 149.95,85.7 v1(150.25,85.99) ; U9.33 v1(150.76,115.12) ; 130.77,84.7 128.61,84.7 127.93,85.38 127.93,87.13 127.65,87.41 125.89,87.41 122.29,83.81 114.08,83.81 112.49,82.21 109.88,82.21 109.64,82.45 R151.1
  BOTTOM w0.121: v1(150.76,115.12) 150.76,108.34 149.31,106.89 149.31,98.98 150.17,98.13 150.17,93.22 149.44,92.49 149.44,87.92 149.92,87.44 149.92,87.43 150,87.36 150.25,87.1 v1(150.25,85.99)
NAND_D12: length 64.8
  TOP w0.121: U9.40 147.26,115.35 v1(147.69,114.92) ; R152.1 112.83,88.57 116.96,88.57 117.3,88.91 129.09,88.91 130.05,89.86 131.39,89.86 132.35,88.91 143.69,88.91 144.87,90.08 v1(148.12,90.08)
  BOTTOM w0.121: v1(147.69,114.92) 147.69,114.77 148.12,114.34 148.12,99.4 147.64,98.92 147.64,94.25 148.12,93.76 v1(148.12,90.08)
NAND_D13: length 73.4
  TOP w0.121: v1(141.96,115.53) 142.52,114.97 144.56,114.97 144.76,115.17 U9.45 ; v1(141.13,93.38) 140.93,93.18 138.29,93.18 137.34,92.24 132.49,92.24 131.99,91.73 129.45,91.73 128.67,92.51 117.24,92.51 115.33,90.6 108.55,90.6 108.54,90.61 106.42,90.61 106.41,90.6 103.44,90.6 103.37,90.54 100.88,90.54 100.88,90.54 97.42,90.54 R153.1
  BOTTOM w0.121: v1(141.96,115.53) 141.78,115.35 141.78,102.23 140.85,101.3 140.85,99.08 141.54,98.4 141.54,94.26 141.58,94.22 141.58,93.82 v1(141.13,93.38)
NAND_D14: length 66.6
  TOP w0.121: v1(143.74,101) 143.25,100.51 138.69,100.51 138.52,100.68 136.92,100.68 136.37,100.13 132.27,100.13 129.72,97.58 124.37,97.58 123.11,98.84 120.05,98.84 118.78,97.57 105.1,97.57 103.32,95.79 100.16,95.79 99.35,94.98 R154.1 ; U9.46 v1(144.26,117.46)
  BOTTOM w0.121: v1(144.26,117.46) 143.79,117 143.79,101.05 v1(143.74,101)
NAND_D15: length 66.2
  TOP w0.121: U9.47 143.76,117.68 143.52,117.92 142.33,117.92 141.23,116.82 139.36,116.82 v1(138.92,117.26) ; R155.1 98.63,96.55 102.55,96.55 104.34,98.34 112.97,98.34 114.49,99.86 130.01,99.86 130.01,99.86 132.8,102.65 136.57,102.65 136.82,102.41 136.82,102.4 v1(137.07,102.15)
  BOTTOM w0.121: v1(137.07,102.15) 137.07,102.52 138.35,103.8 138.35,104.94 138.67,105.26 138.67,117.01 v1(138.92,117.26)
NAND_OEN: length 14.3
  TOP w0.121: v1(147.03,98.08) 146.76,97.81 U9.8 ; R134.1 v1(147.57,104.18)
  BOTTOM w0.121: v1(147.57,104.18) 147.81,103.93 147.81,99.73 147.03,98.94 v1(147.03,98.08)
NAND_WAIT: length 13.9
  TOP w0.121: R133.1 144.51,102.78 144.72,102.98 v1(147.37,102.98) ; U9.7 146.25,97.91 v1(146.26,98.08)
  BOTTOM w0.121: R131.1 146.6,97.75 v1(146.26,98.08) 146.65,98.46 146.65,99.27 147.37,100 v1(147.37,102.98)
NAND_WEN: length 18.6
  TOP w0.121: v1(151.68,98.08) 151.75,98 U9.18 ; R138.1 147.71,105.57 147.76,105.62 v1(150.07,105.62)
  BOTTOM w0.121: v1(150.07,105.62) 150.93,104.77 150.93,101.29 151.95,100.27 151.95,98.36 v1(151.68,98.08)
NAND_WPN: length 17.7
  TOP w0.121: v1(152.44,98.08) 152.25,97.9 U9.19 ; R139.1 141.65,102.02 147,102.02 148.02,101 151.27,101 151.4,101.13 v1(151.4,101.74)
  BOTTOM w0.121: R130.1 v1(152.44,98.08) 152.44,100.7 v1(151.4,101.74)
Net_845: length 0.7
  TOP w0.121: 132.37,162.76 132.37,163.21 v1(132.5,163.38)
PB_INTERRUPT: length 5.7
  BOTTOM w0.121: C118.1 6.9,42.86 6.92,42.89 R156.1 6.92,45.76 6.9,45.78 R113.2 7.02,46.39 R560.1
PHY_LED_10/100N: length 1.6
  TOP w0.121: U25.26 v1(37.1,53.36)
  BOTTOM w0.381: C207.1 36.95,53.5 v1(37.1,53.36)
PHY_LED_1000N: length 52.2
  TOP w0.121: C206.1 v1(38.77,49.44) 38.77,50.08 36.77,52.08 U25.24 ; v1(44.61,7.28) R392.1
  BOTTOM w0.121: v1(38.77,49.44) C206.1 39.23,48.55 45.5,42.28 45.5,8.17 v1(44.61,7.28)
PHY_LED_ACTN: length 67.5
  TOP w0.121: v1(23.63,6.23) 22.92,6.23 R390.1 ; C205.1 v1(37.5,49.44) 37.63,49.57 37.63,50.08 36.36,51.35 35.22,51.35 34.98,51.58 U25.23
  BOTTOM w0.121: v1(23.63,6.23) 24.65,6.23 27.55,9.13 38.98,9.13 43.62,13.78 43.62,41.41 38.09,46.95 38.09,48.09 37.63,48.55 C205.1 v1(37.5,49.44)
PHY_PPS/GPIO: length 2.6
  TOP w0.121: U25.22 34.58,51.38 34.62,51.35 v1(34.62,51.23)
  BOTTOM w0.121: v1(34.62,51.23) 34.62,51.35 34.58,51.39 34.58,52.11 34.84,52.36 R395.1
PM_ALERT: length 21.6
  TOP w0.121: U32.3 63.47,35.15 63.92,35.6 63.92,36.3 v1(65.89,38.26)
  BOTTOM w0.121: v1(65.89,38.26) 65.89,38.33 65.19,39.03 65.19,40.3 R455.1 J17.4 67.22,42.07 69.25,42.07 69.63,42.46 69.63,43.85 70.65,44.87 70.65,46.77 70.9,47.03 U27.3
PM_VDDAADCN: length 5.4
  BOTTOM w0.121: R501.3 46.01,75.35 J27.2 46.37,73.21 46.37,72.83 C372.2
  BOTTOM w0.127: R501.3 46.87,75.35 47.12,75.1
PM_VDDAADCP: length 8.8
  BOTTOM w0.121: C372.1 45.25,72.3 44.05,73.5 44.05,74.9 45.12,75.98 J27.1 46.01,76.11 R501.4
  BOTTOM w0.127: R501.4 46.87,76.11 47.15,76.39
PM_VDDCOREN: length 10
  TOP w0.121: R32.4 66.44,45.78 65.39,46.82 v1(65.39,47.74) 64.63,47.74 64.25,47.36 63.36,47.36 62.7,48.02 61.53,48.02 C353.2
  BOTTOM w0.121: v1(65.39,47.74) 65.6,47.53 U27.9
PM_VDDCOREP: length 7.6
  TOP w0.121: C353.1 62.68,48.68 63.71,47.65 64.08,47.65 64.91,48.49 v1(65.84,48.49) 66.28,48.49 66.32,48.53 R32.3
  BOTTOM w0.121: v1(65.84,48.49) 66.48,48.49 66.63,48.34 U27.10
PM_VDDMPUN: length 5.4
  TOP w0.121: R46.4 70.12,34.1 69.94,34.28 69.94,34.78 C356.2 68.19,35.47 68.01,35.65 U32.9
PM_VDDMPUP: length 4.7
  TOP w0.121: U32.10 68.29,36.15 68.31,36.13 68.9,36.13 C356.1 69.61,36.85 R46.3
PM_VDDSDDRMEMN: length 5
  TOP w0.121: C378.2 120.05,39.66 J41.2 118.14,39.53 R513.4
  TOP w0.127: 117.14,39.81 117.42,39.53 R513.4
PM_VDDSDDRMEMP: length 5
  TOP w0.121: R513.3 118.4,38.78 J41.1 120.18,39.03 120.81,39.03 C378.1
  TOP w0.127: 117.16,38.52 117.42,38.78 R513.3
PM_VDDSDDRN: length 5.6
  TOP w0.121: J20.2 113.63,67.48 R508.4
  TOP w0.127: 113.91,68.68 113.63,68.4 R508.4
  BOTTOM w0.121: C361.2 113.7,67.41 J20.2
PM_VDDSDDRP: length 5.5
  TOP w0.121: R508.3 112.88,67.48 J20.1
  TOP w0.127: 112.63,68.65 112.88,68.4 R508.3
  BOTTOM w0.121: J20.1 111.99,68.55 C361.1
PM_VDDSHV1N: length 5.9
  TOP w0.121: C363.2 121.32,67.47 J26.2
  BOTTOM w0.121: J26.2 121.19,67.6 R493.3
  BOTTOM w0.127: R493.3 121.19,68.46 121.45,68.71
PM_VDDSHV1P: length 5.8
  TOP w0.121: J26.1 119.67,68.11 120.31,68.74 C363.1
  BOTTOM w0.121: J26.1 119.67,67.47 120.43,68.24 120.43,68.32 R493.4
  BOTTOM w0.127: R493.4 120.44,68.46 120.16,68.74
PM_VDDSHV2N: length 5.1
  BOTTOM w0.121: R545.3 113.32,92.88 J38.2 115.86,91.99 C374.2
  BOTTOM w0.127: R545.3 113.32,93.8 113.57,94.05
PM_VDDSHV2P: length 8.1
  BOTTOM w0.121: C374.1 115.35,91.6 114.66,90.91 112.75,90.91 J38.1 112.56,92.88 R545.4
  BOTTOM w0.127: R545.4 112.56,93.8 112.28,94.08
PM_VDDSHV3N: length 6.4
  TOP w0.121: C375.2 135.66,139.47 132.59,139.47 R546.3 131.61,139.67 J39.2
  TOP w0.127: R546.3 132.53,139.67 132.79,139.92
PM_VDDSHV3P: length 6.5
  TOP w0.121: C375.1 135.7,139.21 132.68,139.21 R546.4 131.61,138.92 J39.1
  TOP w0.127: R546.4 132.53,138.92 132.81,138.64
PM_VDDSHV4N: length 5.8
  TOP w0.121: C365.2 139.86,133.01 J30.2
  BOTTOM w0.121: J30.2 137.7,132.24 R494.3
  BOTTOM w0.127: R494.3 135.83,132.24 135.58,132.49
PM_VDDSHV4P: length 5.9
  TOP w0.121: C365.1 139.86,130.47 J30.1
  BOTTOM w0.121: J30.1 137.45,131.49 R494.4
  BOTTOM w0.127: R494.4 135.83,131.49 135.55,131.21
PM_VDDSHV5N: length 5.7
  TOP w0.121: C367.2 100.49,146.21 J32.2
  BOTTOM w0.121: R495.3 101.39,144.05 J32.2
  BOTTOM w0.127: 101.13,142.05 101.39,142.31 R495.3
PM_VDDSHV5P: length 5.7
  TOP w0.121: C367.1 103.03,146.21 J32.1
  BOTTOM w0.121: J32.1 102.14,144.05 R495.4
  BOTTOM w0.127: R495.4 102.14,142.31 102.42,142.03
PM_VDDSHV6N: length 4.8
  BOTTOM w0.121: R496.3 51.29,88.62 J34.2 48.87,89.51 C369.2
  BOTTOM w0.127: 51.03,87.7 51.29,87.95 R496.3
PM_VDDSHV6P: length 8
  BOTTOM w0.121: R496.4 52.04,88.62 J34.1 51.65,90.79 49.14,90.79 C369.1
  BOTTOM w0.127: 52.32,87.67 52.04,87.95 R496.4
PM_VDDSN: length 5.8
  TOP w0.121: 100.62,118.66 100.62,116.62 C370.2
  BOTTOM w0.121: 100.62,118.66 101.51,117.76 R498.3
  BOTTOM w0.127: 101.26,116.27 101.51,116.53 R498.3
PM_VDDSOSCN: length 5.9
  TOP w0.121: J29.2 113.19,58.97 C373.2
  BOTTOM w0.121: R506.3 113.83,61.64 J29.2
  BOTTOM w0.127: R506.3 113.83,62.74 114.08,63
PM_VDDSOSCP: length 5.2
  TOP w0.121: C373.1 112.18,59.41 112.31,59.54 J29.1
  BOTTOM w0.121: J29.1 113.07,61.38 R506.4
  BOTTOM w0.127: 112.79,63.02 113.07,62.74 R506.4
PM_VDDSP: length 5.9
  TOP w0.121: J21.1 103.16,116.88 C370.1
  BOTTOM w0.121: R498.4 102.27,117.76 J21.1
  BOTTOM w0.127: 102.55,116.25 102.27,116.53 R498.4
PM_VDDSRTCN: length 5.5
  BOTTOM w0.121: C379.2 61.38,45.19 J35.2 61.69,47.28 R505.3
  BOTTOM w0.127: R505.3 61.69,48.27 61.95,48.52
PM_VDDSRTCP: length 5.8
  BOTTOM w0.121: C379.1 61.07,44.68 61.07,45.37 J35.1 60.94,47.28 R505.4
  BOTTOM w0.127: 60.66,48.55 60.94,48.27 R505.4
PM_VPLLCRLCDN: length 5.4
  TOP w0.121: C371.2 107.48,58.97 J24.2
  BOTTOM w0.121: J24.2 106.59,61.51 R503.3
  BOTTOM w0.127: R503.3 106.59,62.74 106.84,63
PM_VPLLCRLCDP: length 5.5
  TOP w0.121: C371.1 105.47,58.69 105.47,58.92 104.94,59.45 J24.1
  BOTTOM w0.121: J24.1 105.83,61.51 R503.4
  BOTTOM w0.127: 105.55,63.02 105.83,62.74 R503.4
PM_VPLLDDRN: length 5.5
  BOTTOM w0.121: C368.2 58.33,50.46 J33.2 60.87,53 R507.4
  BOTTOM w0.127: R507.4 60.87,53.98 60.59,54.26
PM_VPLLDDRP: length 8.5
  BOTTOM w0.121: R507.3 61.63,53 J33.1 61.43,51.01 59.68,51.01 59.02,50.35 59.02,49.62 C368.1
  BOTTOM w0.127: R507.3 61.63,53.98 61.88,54.24
PM_VPLLMPUN: length 6.1
  TOP w0.121: 95.29,116.87 95.49,116.67 95.49,114.54 95.16,114.21 C355.2 ; R497.4 95.29,117.64 J22.2
  TOP w0.127: R497.4 95.29,116.78 95.01,116.5
PM_VPLLMPUP: length 6.1
  TOP w0.121: J22.1 95.92,117.77 95.92,117.04 R497.3 95.85,116.72 95.85,114.54 96.18,114.21 C355.1
  TOP w0.127: 96.3,116.53 96.05,116.78 R497.3
PM_VSRAMCOREN: length 5.1
  TOP w0.121: C362.2 44.49,102.91 J23.2
  BOTTOM w0.121: J23.2 46.52,102.27 R500.4
  BOTTOM w0.127: R500.4 47.63,102.27 47.91,102.55
PM_VSRAMCOREP: length 5.1
  TOP w0.121: C362.1 44.23,100.37 J23.1
  BOTTOM w0.121: R500.3 47.03,101.51 J23.1
  BOTTOM w0.127: 47.89,101.26 47.63,101.51 R500.3
PM_VSRAMMPUN: length 4.9
  TOP w0.121: C360.2 44.61,97.45 J25.2
  BOTTOM w0.121: J25.2 46.9,96.55 R499.4
  BOTTOM w0.127: R499.4 47.63,96.55 47.91,96.83
PM_VSRAMMPUP: length 4.8
  TOP w0.121: C360.1 44.61,94.91 J25.1
  BOTTOM w0.121: R499.3 46.9,95.8 J25.1
  BOTTOM w0.127: 47.89,95.54 47.63,95.8 R499.3
PM_VUSB1_8VN: length 5.8
  TOP w0.121: C364.2 114.72,146.47 J28.2 115.61,143.92 R502.4
  TOP w0.127: R502.4 115.61,142.18 115.33,141.9
PM_VUSB1_8VP: length 5.9
  TOP w0.121: C364.1 117.26,145.96 J28.1 116.37,143.92 R502.3
  TOP w0.127: 116.62,141.93 116.37,142.18 R502.3
PM_VUSB3_3VN: length 5.9
  TOP w0.121: R504.4 108.5,143.92 J31.2 107.61,146.21 C366.2
  TOP w0.127: R504.4 108.5,142.18 108.22,141.9
PM_VUSB3_3VP: length 5.8
  TOP w0.121: C366.1 110.15,146.21 J31.1 109.25,143.92 R504.3
  TOP w0.127: 109.51,141.93 109.25,142.18 R504.3
PMIC_DELAYEDRTCPORZ: length 1.6
  TOP w0.121: R3.1 U1.2
PMIC_GPIO: length 127.6
  TOP w0.121: R3.2 59.27,101.97 59.27,99.66 60.04,98.88 60.18,98.88 v1(60.49,98.57) ; C114.1 R69.1 94.53,24.17 94.27,24.42 92.95,24.42 92.06,25.31 86.79,25.31 86.4,25.7 86.4,26.45 85.89,26.96 81.46,26.96 80.98,26.48 79.51,26.48 78.02,27.98 v1(78.02,29.5) ; v1(56.5,39.79) 56.62,39.67 78.51,39.67 80.67,37.51 v1(82.21,37.51)
  BOTTOM w0.121: v1(60.49,98.57) 60.49,98.13 60.6,98.01 60.6,95.38 59.55,94.32 59.55,93.66 59.55,92.16 59.46,92.07 59.46,89.56 59.46,89.15 60.6,88.01 60.6,87.42 60.6,87.01 61.32,86.29 61.32,83.38 61.96,82.74 61.96,81.32 61.99,81.29 61.99,81.25 62.37,80.86 62.37,72.98 61.71,72.32 58.46,69.06 58.46,58.08 57.39,57.01 57.39,40.67 v1(56.5,39.79) ; v1(78.02,29.5) 78.02,30.14 78.86,30.98 80.64,30.98 81.06,31.41 81.06,33.95 82.59,35.47 82.59,37.13 v1(82.21,37.51)
PMIC_I2C_SCL: length 149.5
  TOP w0.121: R55.1 131.23,94.31 131.54,94.63 131.54,94.71 132.37,95.54 137.08,95.54 137.97,96.43 137.97,97.91 138.89,98.84 141.36,98.84 v1(141.54,99.02) ; v1(121.58,58.2) 122.08,58.2 122.79,58.9 129.01,58.9 129.08,58.84 131.8,58.84 133.2,57.44 139.74,57.44 v1(140.58,58.28)
  TOP w0.203: v1(90.84,28.99) 90.84,29.55 90.45,29.95 U4.9
  LY3 w0.133: v1(90.84,28.99) 90.84,28.55 88.81,26.52 v1(85.36,26.52)
  BOTTOM w0.121: R551.1 84.26,25.06 85.36,26.15 v1(85.36,26.52) ; v1(141.54,99.02) 141.54,98.75 141.81,98.48 141.81,94.31 141.82,94.3 141.82,93.95 142.29,93.49 142.29,88.44 143.1,87.63 143.1,82.91 143.29,82.72 143.29,76.78 141.9,75.38 141.9,72.08 141.38,71.57 141.38,66.72 140.6,65.94 140.6,58.74 140.58,58.71 v1(140.58,58.28) ; v1(90.84,28.99) 91.21,28.99 93.05,27.15 95.41,27.15 101.38,21.18 106.65,21.18 106.67,21.2 106.77,21.2 109.13,23.57 109.13,25.44 112.37,28.68 112.37,38.32 121.07,47.02 121.07,57.7 v1(121.58,58.2)
PMIC_I2C_SDA: length 115.3
  TOP w0.121: v1(84.44,26.52) 84.25,26.71 81.56,26.71 81.05,26.2 79.31,26.2 74.48,31.03 v1(57.7,31.03) ; v1(60.68,93.76) 60.68,94.43 61.04,94.79 63.92,94.79 64.76,93.95 65.55,93.95 66.07,93.43 66.24,93.43 66.41,93.26 67.85,93.26 68.36,92.75 R56.1 ; U4.8 90.05,29.66 v1(90.21,29.5)
  LY3 w0.133: v1(90.21,29.5) 87.92,27.22 85.14,27.22 v1(84.44,26.52)
  BOTTOM w0.121: v1(57.7,31.03) 57.38,31.34 57.38,39.81 57.63,40.07 57.63,56.87 59.41,58.65 59.41,69.31 61.63,71.53 62.87,72.77 62.87,81.07 62.53,81.4 62.53,81.44 62.48,81.5 62.48,81.51 62.45,81.54 62.45,82.95 61.82,83.58 61.82,86.49 61.1,87.21 61.1,88.22 59.96,89.36 59.96,91.87 60.05,91.96 60.05,93.13 v1(60.68,93.76) ; v1(84.44,26.52) 84.12,26.2 R550.1
